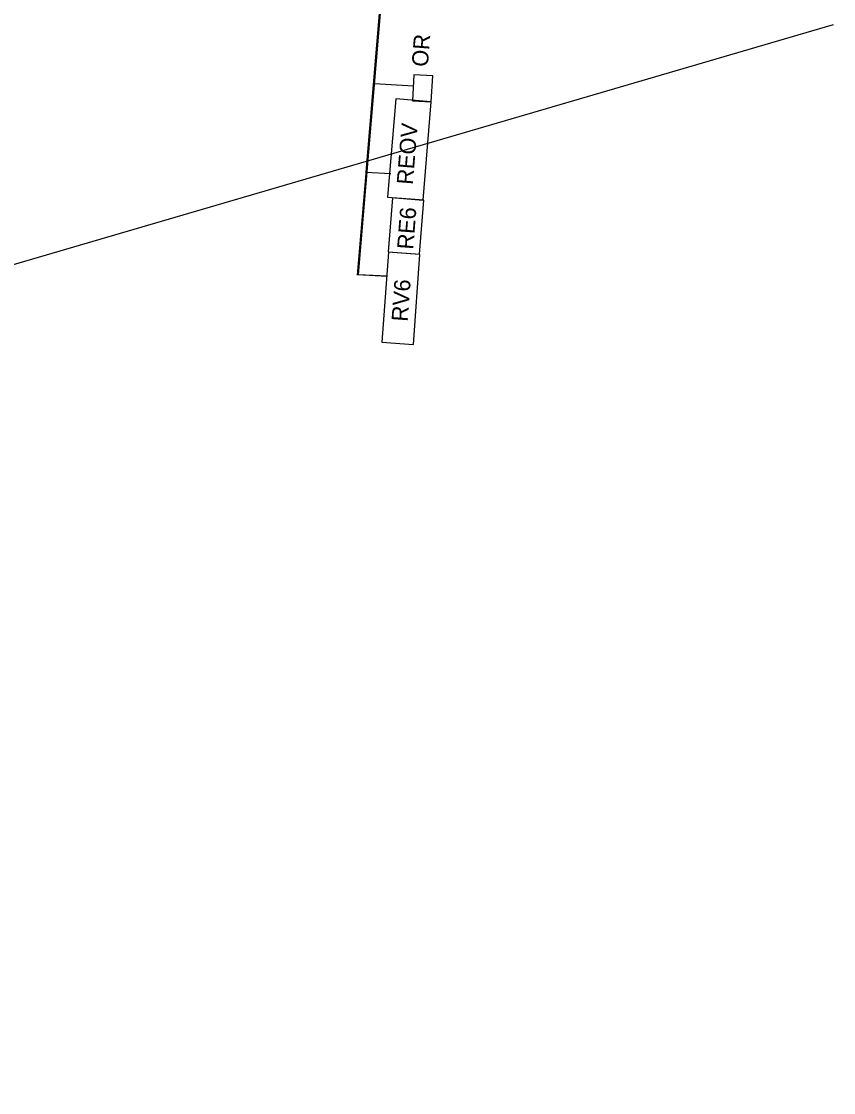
# Model space of a CAD drawing. Extents: x -669628 to -669207, y -977198 to -977075.
# Drawn here: x -669522.25 to -669513.23, y -977164.78 to -977152.89 of the extents above; entities that cross this region are included whole.
import ezdxf

# ---------------------------------------------------------------- set-up
doc = ezdxf.new("R2010")
doc.units = 0
for name, color, linetype in [('_PS_SO_číslo', 7, 'Continuous'), ('SO 01-86-01', 7, 'Continuous'), ('Stávající', 7, 'Continuous')]:
    doc.layers.add(name, color=color, linetype=linetype)

msp = doc.modelspace()

# ---------------------------------------------------------------- linework, layer by layer
at = {"layer": '_PS_SO_číslo'}
msp.add_line((-669553.762, -977164.778), (-669513.231, -977152.923), dxfattribs=at)
at = {"layer": 'SO 01-86-01'}
for p, q in [((-669517.763, -977146.78), (-669518.52, -977155.707)), ((-669517.763, -977146.78), (-669518.507, -977155.699)), ((-669517.763, -977146.78), (-669518.424, -977154.562)), ((-669517.89, -977153.481), (-669517.906, -977153.771)), ((-669517.681, -977153.493), (-669517.89, -977153.481)), ((-669517.698, -977153.783), (-669517.681, -977153.493)), ((-669517.895, -977153.61), (-669518.331, -977153.581)), ((-669518.092, -977153.75), (-669518.181, -977154.842)), ((-669517.698, -977153.783), (-669518.092, -977153.75)), ((-669517.906, -977153.771), (-669517.698, -977153.783)), ((-669517.787, -977154.874), (-669517.698, -977153.783)), ((-669518.424, -977154.562), (-669518.147, -977154.579)), ((-669518.181, -977154.842), (-669517.787, -977154.874)), ((-669518.171, -977155.452), (-669518.244, -977156.45)), ((-669517.822, -977155.478), (-669518.171, -977155.452)), ((-669517.822, -977155.478), (-669518.171, -977155.452)), ((-669517.895, -977156.475), (-669517.822, -977155.478)), ((-669517.895, -977156.475), (-669517.822, -977155.478)), ((-669518.515, -977155.7), (-669518.186, -977155.718)), ((-669518.507, -977155.699), (-669518.183, -977155.713)), ((-669518.244, -977156.45), (-669517.895, -977156.475))]:
    msp.add_line(p, q, dxfattribs=at)
at = {"layer": 'Stávající'}
for p, q in [((-669518.129, -977154.848), (-669518.175, -977155.447)), ((-669517.78, -977154.875), (-669518.129, -977154.848)), ((-669517.826, -977155.473), (-669517.78, -977154.875)), ((-669518.175, -977155.447), (-669517.826, -977155.473))]:
    msp.add_line(p, q, dxfattribs=at)

# ---------------------------------------------------------------- texts
at = {"layer": 'SO 01-86-01'}
for s, rotation, p in [('OR', 85.6742, (-669517.735, -977153.398)), ('REOV', 85.3123, (-669517.902, -977154.707)), ('RV6', 85.8169, (-669517.959, -977156.226))]:
    msp.add_text(s, height=0.18, rotation=rotation, dxfattribs=at).set_placement(p)
at = {"layer": 'Stávající'}
msp.add_text('RE6', height=0.18, rotation=85.6742, dxfattribs=at).set_placement((-669517.897, -977155.426))

doc.saveas('drawing.dxf')
